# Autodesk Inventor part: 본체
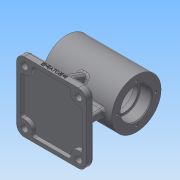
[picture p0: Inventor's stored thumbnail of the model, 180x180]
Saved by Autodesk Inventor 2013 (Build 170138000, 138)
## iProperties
Created: 2019-06
Part Number: 본체
Material: 일반
Document SubType Name: Modeling
Designer: Administrator
Density: 1 g/cm^3
Author: Administrator
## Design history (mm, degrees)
sketch "스케치1"
  geometry: L1 (-45, 32)-(-45, 20); L2 (-45, 20)-(-30, 20); L3 (-30, 20)-(-30, 17); L4 (-30, 17)-(-24, 17); L5 (-24, 17)-(-24, 25); L6 (-24, 25)-(24, 25); L7 (24, 25)-(24, 17); L8 (24, 17)-(30, 17); L9 (30, 17)-(30, 20); L10 (30, 20)-(45, 20); L11 (45, 20)-(45, 32); L12 (45, 32)-(-45, 32); L13 (-45, 0)-(45, 0); 2 further points
  constraints: 26 end point, 4 vertical, 2 point on line, 1 coincident, 1 horizontal, 1 midpoint
  dimensions: "d0" = 90 distance of L13.start L13.end; "d3" = 34 diameter of L4 L13; "d4" = 34 diameter of L8 L13; "d5" = 50 diameter of L6 L13; "d6" = 40 diameter of L2 L13; "d7" = 40 diameter of L10 L13; "d8" = 64 diameter of L12 L13; "d9" = 15 distance of L1.end L2.end; "d10" = 48 distance of L5.end L6.end; "d11" = 90 distance of L11.end L1.start; "d12" = 15 distance of L9.end L10.end; "d13" = 6 distance of L3.end L4.end; "d14" = 6 distance of L7.end L8.end
revolve "회전1" sketch "스케치1" stored, may be unused: angle "d15" = 90 deg
node "작업 평면1"
sketch "스케치2"
  geometry: L1 (45, -45)-(-45, -45); L2 (-45, -45)-(-45, 45); L3 (-45, 45)-(45, 45); L4 (45, 45)-(45, -45); L5 (45, -45)-(-45, 45); L6 (-45, -45)-(45, 45); 3 further points
  constraints: 12 end point, 3 midpoint, 2 parallel, 1 coincident, 1 horizontal, 1 perpendicular
  dimensions: "d17" = 90 distance of L2.end L3.end; "d18" = 90 distance of L1.end L2.end
extrude "돌출1" join sketch "스케치2" distance "d19" = 10; taper "d20" = 0 deg
sketch "스케치3"
  geometry: L1 (45, 45)-(45, -45) reference; L2 (-35, 5)-(35, 5); L3 (35, 5)-(35, -5); L4 (35, -5)-(-35, -5); L5 (-35, -5)-(-35, 5); 2 further points
  constraints: 8 end point, 2 parallel, 1 horizontal, 1 horizontal alignment, 1 midpoint, 1 perpendicular
  dimensions: "d28" = 70 distance of L2.start L2.end; "d30" = 10 distance of L2.end L3.end; "d31" = 10 distance between parallel lines of L1 L3
extrude "돌출2" join sketch "스케치3" stored distance "d32" = 10; taper "d33" = 0 deg
sketch "스케치4"
  geometry: L1 (-22.189, -23.058)-(-55, -35); L2 (-55, -45)-(-55, 45) reference; L3 (-65, -45)-(-55, -45) reference; 2 further points
  constraints: 2 end point, 1 point on line, 2 other
  dimensions: "d34" = 10 distance from line of L1.end L3; "d35" = 110 deg angle of L1 L2
feature "리브1" sketch "스케치4" dims "d36" = 1, "d37" = 10, "d38" = 0, "d39" = 0, "d40" = 1, "d41" = 1
node "작업 평면2"
sketch "스케치5"
  geometry: C1 r 5 at (0, 0); 1 further point
  constraints: 1 centre point, 1 coincident
  dimensions: "d43" = 10 diameter of C1
extrude "돌출3" join sketch "스케치5" stored distance "d44" = 10; taper "d45" = 0 deg
hole "구멍1" diameter "d48" = 4.917; stored, may be unused: countersink angle "d52" = 90 deg, drill point angle "d54" = 118 deg; dims "d46" = 10, "d47" = 10, "d49" = 6, "d50" = 4, "d51" = 2, "d53" = 8
sketch "스케치6"
  geometry: 2 further points
  constraints: 1 vertical alignment
  dimensions: "d55" = 25 distance of point (0, 25) point (0, 0)
hole "구멍2" sketch "스케치6" at (0, 25) diameter "d56" = 3.242; stored, may be unused: countersink angle "d60" = 90 deg, drill point angle "d62" = 118 deg; dims "d57" = 7, "d58" = 4, "d59" = 2, "d61" = 9
fillet "모깎기1" dims "d66" = 10
hole "구멍3" diameter "d69" = 9; stored, may be unused: countersink angle "d73" = 90 deg, drill point angle "d75" = 118 deg; dims "d67" = 10, "d68" = 10, "d70" = 7, "d71" = 4, "d72" = 2, "d74" = 9
sketch "스케치7"
  geometry: L1 (-26.34, 40)-(26.34, 40); L2 (-40, 26.34)-(-40, 0); L3 (-40, 0)-(40, 0); L4 (40, 0)-(40, 26.34); L5 (-26.34, -40)-(26.34, -40); L6 (-40, -26.34)-(-40, 0); L7 (40, 0)-(40, -26.34); C1 r 4.5 at (-35, 35) reference; C2 r 4.5 at (35, 35) reference; C3 r 4.5 at (-35, -35); C4 r 4.5 at (35, -35); A1 r 10 centre (-35, 35) between (-40, 26.34) and (-26.34, 40); A2 r 10 centre (35, 35) between (26.34, 40) and (40, 26.34); A3 r 10 centre (-35, -35) between (-26.34, -40) and (-40, -26.34); A4 r 10 centre (35, -35) between (40, -26.34) and (26.34, -40); 1 further point
  constraints: 14 end point, 8 point on circle, 8 symmetric about line, 6 centre point, 4 coincident, 2 vertical, 1 horizontal, 1 midpoint, 4 other
  dimensions: "d76" = 10 radius of A1; "d77" = 10 radius of A2; "d78" = 40 distance from line of point (0, 0) L1; "d79" = 52.67949 distance of L1.start L1.end; "d80" = 40 distance from line of point (0, 0) L2; "d81" = 40 distance from line of point (0, 0) L4
extrude "돌출4" cut sketch "스케치7" distance "d82" = 5; taper "d83" = 0 deg
fillet "모깎기2" dims "d84" = 3
fillet "모깎기3" dims "d85" = 3
fillet "모깎기4" dims "d86" = 3, "d87" = 0.6
chamfer "모따기1" distance "d88" = 1; stored, may be unused: second distance "d89" = 2, angle "d90" = 45 deg
fillet "모깎기5" dims "d91" = 2
sketch "스케치8"
  geometry: L1 (-10, 7)-(-10, 0) reference; L2 (70, 0)-(0, 0) reference; 2 further points
  constraints: 1 other
  dimensions: "d92" = 45 distance from line of L1 point (35, 4); "d96" = 4 distance from line of point (35, 4) L2
feature "엠보싱1" sketch "스케치8" dims "d0" = 90, "d3" = 34, "d4" = 34, "d5" = 50, "d6" = 40, "d7" = 40, "d8" = 64, "d9" = 15, "d10" = 48, "d11" = 90, "d12" = 15, "d13" = 6, "d14" = 6, "d17" = 90, "d18" = 90, "d94" = 0.5, "d95" = 0
node "솔리드1"
mirror "대칭1"
pattern_circular "원형 패턴1" dims angle "d64" = 360 deg
mirror "대칭2"
mirror "대칭3"
mirror "대칭4"
other parameters: "d16" = -65, "d42" = 35
